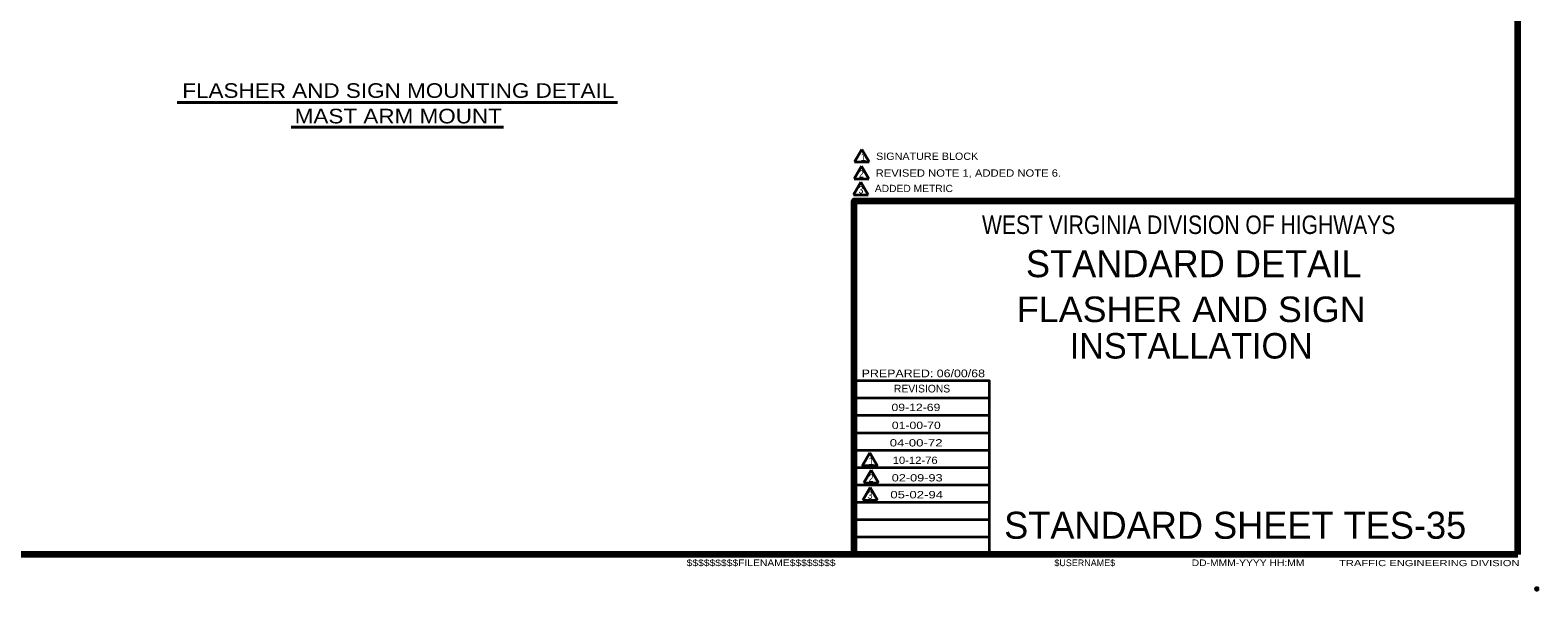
# Model space of a CAD drawing. Extents: x -31 to 825, y 0 to 544.
# Drawn here: x 329.4 to 824.6, y 0.2 to 184.2 of the extents above; entities that cross this region are included whole.
import ezdxf
from ezdxf.enums import TextEntityAlignment as Align

# ---------------------------------------------------------------- set-up
doc = ezdxf.new("R2010")
doc.units = 0
doc.header["$LTSCALE"] = 1.2
doc.header["$PDMODE"] = 32
doc.header["$PDSIZE"] = 0.6
doc.layers.add('1', color=7, linetype='Continuous', lineweight=53)
doc.layers.add('61', color=7, linetype='Continuous', lineweight=35)

msp = doc.modelspace()

# ---------------------------------------------------------------- linework, layer by layer
at = {"layer": '1', "lineweight": 158}
for q in [(818.018, 537.903), (818.018, 128.103), (26.418, 11.803)]:
    msp.add_line((818.018, 11.803), q, dxfattribs=at)
at = {"layer": '1', "lineweight": 13}
msp.add_line((818.018, 11.803), (818.018, 537.903), dxfattribs=at)
at = {"layer": '1', "lineweight": 40}
for p, q in [((377.727, 160.434), (522.334, 160.434)), ((415.163, 152.306), (484.852, 152.306))]:
    msp.add_line(p, q, dxfattribs=at)
at = {"layer": '1', "lineweight": 35}
for p, q in [((602.6, 145.035), (600.2, 140.878)), ((605, 140.878), (602.6, 145.035)), ((602.455, 139.52), (600.055, 135.363)), ((600.2, 140.878), (605, 140.878)), ((604.855, 135.363), (602.455, 139.52)), ((602.286, 134.265), (599.885, 130.108)), ((600.055, 135.363), (604.855, 135.363)), ((604.686, 130.108), (602.286, 134.265)), ((599.885, 130.108), (604.686, 130.108)), ((644.518, 63.203), (600.018, 63.203)), ((644.518, 57.503), (600.018, 57.503)), ((644.518, 51.703), (600.018, 51.703)), ((644.518, 46.003), (600.018, 46.003)), ((644.518, 40.303), (600.018, 40.303)), ((605.646, 39.523), (603.246, 35.367)), ((603.246, 35.367), (608.046, 35.367)), ((608.046, 35.367), (605.646, 39.523)), ((644.518, 34.603), (600.018, 34.603)), ((605.321, 33.894), (602.921, 29.737)), ((602.921, 29.737), (607.721, 29.737)), ((607.721, 29.737), (605.321, 33.894)), ((644.518, 28.903), (600.018, 28.903)), ((644.518, 23.203), (600.018, 23.203)), ((644.518, 17.503), (600.018, 17.503))]:
    msp.add_line(p, q, dxfattribs=at)
at = {"layer": '1', "lineweight": 158}
msp.add_lwpolyline([(600.018, 11.803), (600.018, 128.103), (818.018, 128.103)], dxfattribs=at)
at = {"layer": '1', "lineweight": 35}
msp.add_lwpolyline([(644.518, 11.803), (644.518, 68.903), (600.018, 68.903)], dxfattribs=at)
msp.add_lwpolyline([(605.203, 45.205), (602.803, 41.048), (607.603, 41.048)], close=True, dxfattribs=at)
at = {"layer": '1'}
msp.add_point((824.318, 0.503), dxfattribs=at)
at = {"layer": '61', "lineweight": 53}
for q in [(665.318, 11.803), (665.318, 11.803), (665.318, 11.803), (665.618, 11.803), (665.618, 11.803)]:
    msp.add_line((818.018, 11.803), q, dxfattribs=at)

# ---------------------------------------------------------------- texts
at = {"layer": '1'}
for s, height, width, p in [('FLASHER AND SIGN MOUNTING DETAIL', 4.8, 1.15, (450.315, 161.963)), ('MAST ARM MOUNT', 4.8, 1.15, (450.315, 153.563)), ('WEST VIRGINIA DIVISION OF HIGHWAYS', 6.089, 0.85, (709.918, 117.203)), ('FLASHER AND SIGN', 8.391, 1.05, (710.767, 88.249)), ('09-12-69', 2.4, 1.25, (620.33, 58.996)), ('01-00-70', 2.4, 1.25, (620.462, 53.095)), ('04-00-72', 2.4, 1.35, (620.408, 47.348)), ('10-12-76', 2.4, 1.15, (620.097, 41.602)), ('02-09-93', 2.4, 1.3, (620.745, 35.849)), ('05-02-94', 2.4, 1.35, (620.6, 30.305))]:
    msp.add_text(s, height=height, dxfattribs=dict(at, width=width)).set_placement(p, align=Align.CENTER)
for s, height, p in [('1', 2.4, (602.214, 141.28)), ('REVISIONS', 2.537, (613.118, 65.103)), ('1', 2.4, (604.731, 41.37)), ('STANDARD SHEET TES-35', 8.881, (649.318, 17.003)), ('$USERNAME$', 2.2, (665.818, 8.003))]:
    msp.add_text(s, height=height, dxfattribs=at).set_placement(p)
for s, height, width, p in [('SIGNATURE BLOCK', 2.4, 1.1, (607.261, 141.561)), ('2', 2.4, 0.9, (601.633, 135.765)), ('REVISED NOTE 1, ADDED NOTE 6.', 2.4, 1.15, (607.116, 136.046)), ('3', 2.4, 0.9, (601.464, 130.51)), ('ADDED METRIC', 2.4, 1.05, (606.847, 130.984)), ('PREPARED: 06/00/68', 2.537, 1.2, (602.518, 70.103)), ('2', 2.4, 0.9, (604.824, 35.768)), ('3', 2.4, 0.9, (604.499, 30.139)), ('$$$$$$$$$FILENAME$$$$$$$$', 2.2, 1.15, (545.018, 8.003)), ('DD-MMM-YYYY HH:MM', 2.2, 1.15, (710.918, 8.003)), ('TRAFFIC ENGINEERING DIVISION', 2.031, 1.35, (759.318, 8.003))]:
    msp.add_text(s, height=height, dxfattribs=dict(at, width=width)).set_placement(p)
for s, height, p in [('STANDARD DETAIL', 8.881, (711.568, 103.003)), ('INSTALLATION', 8.391, (710.767, 76.253))]:
    msp.add_text(s, height=height, dxfattribs=at).set_placement(p, align=Align.CENTER)

doc.saveas('drawing.dxf')
